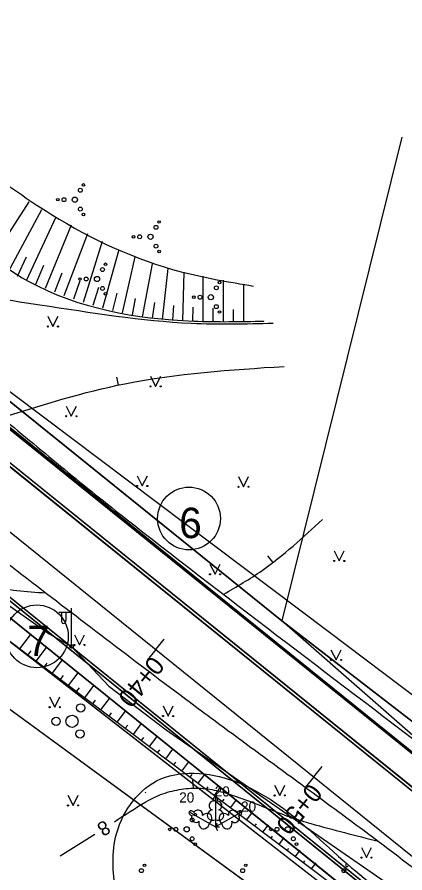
# Model space of a CAD drawing. Extents: x 514086 to 514457, y 297399 to 297567.
# Drawn here: x 514162.8 to 514181.92, y 297461.26 to 297503.43 of the extents above; entities that cross this region are included whole.
import ezdxf

# ---------------------------------------------------------------- set-up
doc = ezdxf.new("R2010")
doc.units = 0
for name, color, linetype in [('AA_Apzimejumi', 7, 'Continuous'), ('AA_Brauktuve', 7, 'Continuous'), ('AA_cela_mala', 7, 'Continuous'), ('AA_Ielas_ass', 7, 'Continuous'), ('AA_Ietve', 7, 'Continuous'), ('AA_nogaze', 7, 'Continuous'), ('AA_Nomale', 7, 'Continuous'), ('AA_Zale', 7, 'Continuous'), ('Level 1', 7, 'Continuous'), ('Level 21', 7, 'Continuous'), ('Level 23', 7, 'Continuous'), ('Level 29', 7, 'Continuous'), ('Level 31', 7, 'Continuous'), ('Level 32', 7, 'Continuous'), ('Level 37', 7, 'Continuous'), ('Level 44', 7, 'Continuous'), ('Level 45', 7, 'Continuous'), ('Level 46', 7, 'Continuous'), ('Level 8', 7, 'Continuous')]:
    doc.layers.add(name, color=color, linetype=linetype)

msp = doc.modelspace()

# ---------------------------------------------------------------- linework, layer by layer
at = {"layer": 'AA_Apzimejumi'}
for centre in [(514171.276, 297478.727), (514163.781, 297472.919)]:
    msp.add_circle(centre, 1.546, dxfattribs=at)
at = {"layer": 'AA_Brauktuve'}
for points in [[(514184.371, 297463.607), (514146.894, 297493.805)], [(514139.852, 297493.058), (514181.234, 297459.714)]]:
    msp.add_lwpolyline(points, dxfattribs=at)
at = {"layer": 'AA_cela_mala'}
for p, q in [((514185.262, 297464.713), (514147.785, 297494.911)), ((514147.835, 297494.973), (514185.313, 297464.775)), ((514146.894, 297493.805), (514184.371, 297463.607)), ((514184.466, 297463.724), (514146.988, 297493.922)), ((514139.758, 297492.942), (514181.14, 297459.597)), ((514139.852, 297493.058), (514181.234, 297459.714))]:
    msp.add_line(p, q, dxfattribs=at)
at = {"layer": 'AA_Ielas_ass'}
for p, q in [((514159.568, 297480.383), (514182.803, 297461.661)), ((514169.637, 297472.27), (514170.05, 297472.782)), ((514169.637, 297472.27), (514169.224, 297471.757)), ((514177.423, 297465.995), (514177.836, 297466.508)), ((514177.423, 297465.995), (514177.011, 297465.483))]:
    msp.add_line(p, q, dxfattribs=at)
at = {"layer": 'AA_Ietve'}
for points in [[(514185.262, 297464.713), (514147.791, 297494.906)], [(514146.982, 297493.927), (514184.466, 297463.724)]]:
    msp.add_lwpolyline(points, dxfattribs=at)
at = {"layer": 'AA_nogaze'}
for p, q in [((514162.943, 297472.302), (514163.47, 297473.001)), ((514163.343, 297472.001), (514163.498, 297472.207)), ((514163.742, 297471.7), (514164.249, 297472.373)), ((514164.54, 297471.098), (514165.028, 297471.745)), ((514164.141, 297471.399), (514164.29, 297471.597)), ((514164.939, 297470.797), (514165.083, 297470.988)), ((514165.339, 297470.496), (514165.807, 297471.117)), ((514165.738, 297470.195), (514165.876, 297470.378)), ((514166.137, 297469.894), (514166.586, 297470.49)), ((514166.536, 297469.593), (514166.668, 297469.768)), ((514166.936, 297469.292), (514167.365, 297469.862)), ((514167.335, 297468.991), (514167.461, 297469.158)), ((514167.734, 297468.69), (514168.144, 297469.234)), ((514168.133, 297468.389), (514168.254, 297468.549)), ((514168.533, 297468.088), (514168.923, 297468.606)), ((514168.932, 297467.787), (514169.046, 297467.939)), ((514169.331, 297467.486), (514169.702, 297467.979)), ((514169.73, 297467.185), (514169.839, 297467.329)), ((514170.13, 297466.884), (514170.482, 297467.352)), ((514170.529, 297466.583), (514170.632, 297466.721)), ((514170.928, 297466.282), (514171.266, 297466.731)), ((514171.327, 297465.981), (514171.427, 297466.113)), ((514171.727, 297465.68), (514172.051, 297466.11)), ((514172.126, 297465.379), (514172.221, 297465.505)), ((514172.525, 297465.078), (514172.835, 297465.49)), ((514172.924, 297464.777), (514173.015, 297464.898)), ((514173.323, 297464.476), (514173.62, 297464.869)), ((514173.723, 297464.175), (514173.809, 297464.29)), ((514174.122, 297463.874), (514174.404, 297464.248)), ((514174.521, 297463.573), (514174.604, 297463.682)), ((514174.92, 297463.272), (514175.188, 297463.627)), ((514175.32, 297462.971), (514175.398, 297463.075)), ((514175.719, 297462.67), (514175.973, 297463.007)), ((514176.118, 297462.369), (514176.192, 297462.467)), ((514176.517, 297462.068), (514176.757, 297462.386)), ((514176.917, 297461.767), (514176.986, 297461.86)), ((514177.316, 297461.466), (514177.542, 297461.765))]:
    msp.add_line(p, q, dxfattribs=at)
msp.add_lwpolyline([(514139.381, 297492.411), (514153.448, 297479.653), (514157.356, 297476.515), (514190.113, 297451.817)], dxfattribs=at)
at = {"layer": 'AA_Nomale'}
for points in [[(514181.14, 297459.597), (514139.77, 297492.933)], [(514139.413, 297492.389), (514139.411, 297492.386), (514180.732, 297459.091)]]:
    msp.add_lwpolyline(points, dxfattribs=at)
at = {"layer": 'AA_Zale'}
for p, q in [((514146.591, 297497.26), (514175.859, 297473.677)), ((514139.35, 297492.435), (514180.732, 297459.091)), ((514175.859, 297473.677), (514193.845, 297459.804))]:
    msp.add_line(p, q, dxfattribs=at)
for points in [[(514197.26, 297461.293), (514196.873, 297461.611), (514193.845, 297459.804), (514175.859, 297473.677), (514146.591, 297497.26)], [(514147.835, 297494.973), (514185.313, 297464.775)], [(514180.732, 297459.091), (514139.411, 297492.386), (514139.381, 297492.411)], [(514139.036, 297492.046), (514153.448, 297479.653), (514180.419, 297458.702)], [(514139.139, 297491.971), (514139.135, 297491.966), (514153.455, 297479.647), (514180.419, 297458.702)]]:
    msp.add_lwpolyline(points, dxfattribs=at)
at = {"layer": 'Level 1'}
for p, q in [((514172.279, 297463.703), (514172.58, 297463.53)), ((514172.58, 297463.877), (514172.58, 297463.53)), ((514172.58, 297463.53), (514172.68, 297463.703)), ((514172.881, 297463.703), (514172.58, 297463.53)), ((514172.58, 297463.53), (514172.78, 297463.53)), ((514172.58, 297463.53), (514172.68, 297463.357))]:
    msp.add_line(p, q, dxfattribs=at)
for points in [[(514172.58, 297465.03), (514172.58, 297463.877)], [(514172.67, 297464.798), (514172.669, 297464.799)], [(514171.281, 297464.28), (514172.279, 297463.703)], [(514171.527, 297464.241), (514171.526, 297464.241)], [(514173.879, 297464.28), (514172.881, 297463.703)], [(514173.723, 297464.086), (514173.723, 297464.088)]]:
    msp.add_lwpolyline(points, dxfattribs=at)
for centre, radius in [((514165.936, 297469.392), 0.207), ((514164.725, 297468.732), 0.204), ((514165.509, 297468.732), 0.301), ((514165.904, 297468.112), 0.205)]:
    msp.add_circle(centre, radius, dxfattribs=at)
for centre, major_axis, ratio, start_param, end_param in [((514172.58, 297464.88), (0, -0.15), 0.707107, 3.14537, 5.287485), ((514172.58, 297464.88), (0, -0.15), 0.707107, 0.995701, 3.137816), ((514172.452, 297464.585), (-0.039, -0.212), 0.861323, 3.141593, 6.283185), ((514172.708, 297464.585), (0.039, -0.212), 0.861323, 0, 3.141593), ((514171.411, 297464.205), (0.13, -0.075), 0.707107, 3.14537, 5.287485), ((514171.411, 297464.205), (0.13, -0.075), 0.707107, 0.995701, 3.137816), ((514171.602, 297463.946), (0.165, -0.14), 0.861323, 3.141593, 6.283185), ((514171.73, 297464.169), (0.203, -0.073), 0.861323, 0, 3.141593), ((514172.111, 297463.904), (-0.236, -0.218), 0.814445, 1.531171, 4.712389), ((514172.49, 297464.123), (0.307, 0.095), 0.814445, 1.570796, 4.752015), ((514172.67, 297464.123), (-0.307, 0.095), 0.814445, 1.531171, 4.712389), ((514173.049, 297463.904), (0.236, -0.218), 0.814445, 1.570796, 4.752015), ((514173.43, 297464.169), (-0.203, -0.073), 0.861323, 3.141593, 6.283185), ((514173.558, 297463.946), (-0.165, -0.14), 0.861323, 0, 3.141593), ((514173.749, 297464.205), (-0.13, -0.075), 0.707107, 3.14537, 5.287485), ((514173.749, 297464.205), (-0.13, -0.075), 0.707107, 0.995701, 3.137816), ((514172.022, 297463.749), (0.071, 0.313), 0.814445, 1.570796, 4.752015), ((514173.138, 297463.749), (-0.071, 0.313), 0.814445, 1.531171, 4.712389)]:
    msp.add_ellipse(centre, major_axis=major_axis, ratio=ratio, start_param=start_param, end_param=end_param, dxfattribs=at)
at = {"layer": 'Level 21'}
for points in [[(514157.951, 297499.728), (514156.119, 297498.271), (514154.804, 297496.296), (514155.649, 297494.512), (514158.938, 297490.653), (514163.925, 297489.256), (514171.388, 297488.349), (514175.429, 297488.349)], [(514167.656, 297460.196), (514167.656, 297463.017), (514169.677, 297465.792), (514173.482, 297465.792), (514178.65, 297462.077), (514185.698, 297456.857), (514187.671, 297455.211), (514188.469, 297452.531), (514186.966, 297450.274), (514184.429, 297447.265)]]:
    msp.add_spline(points, degree=3, dxfattribs=at)
at = {"layer": 'Level 23'}
for p, q in [((514164.32, 297488.688), (514164.57, 297488.188)), ((514164.57, 297488.188), (514164.82, 297488.688)), ((514169.38, 297485.735), (514169.63, 297485.235)), ((514169.63, 297485.235), (514169.88, 297485.735)), ((514165.226, 297484.266), (514165.476, 297483.766)), ((514165.476, 297483.766), (514165.726, 297484.266)), ((514168.724, 297480.828), (514168.974, 297480.328)), ((514168.974, 297480.328), (514169.224, 297480.828)), ((514173.714, 297480.789), (514173.964, 297480.289)), ((514173.964, 297480.289), (514174.214, 297480.789)), ((514178.43, 297477.133), (514178.68, 297476.633)), ((514178.68, 297476.633), (514178.93, 297477.133)), ((514172.308, 297476.476), (514172.558, 297475.976)), ((514172.558, 297475.976), (514172.808, 297476.476)), ((514165.624, 297472.994), (514165.874, 297472.494)), ((514165.874, 297472.494), (514166.124, 297472.994)), ((514178.274, 297472.258), (514178.524, 297471.758)), ((514178.524, 297471.758), (514178.774, 297472.258)), ((514164.406, 297469.932), (514164.656, 297469.432)), ((514164.656, 297469.432), (514164.906, 297469.932)), ((514169.996, 297469.494), (514170.246, 297468.994)), ((514170.246, 297468.994), (514170.496, 297469.494)), ((514175.497, 297465.58), (514175.747, 297465.08)), ((514175.747, 297465.08), (514175.997, 297465.58)), ((514165.311, 297465.088), (514165.561, 297464.588)), ((514165.561, 297464.588), (514165.811, 297465.088)), ((514179.776, 297462.517), (514180.026, 297462.017)), ((514180.026, 297462.017), (514180.276, 297462.517))]:
    msp.add_line(p, q, dxfattribs=at)
for centre, radius in [((514166.07, 297495.161), 0.064), ((514165.918, 297494.898), 0.096), ((514164.811, 297494.434), 0.064), ((514165.114, 297494.434), 0.096), ((514165.65, 297494.434), 0.128), ((514165.918, 297493.97), 0.096), ((514166.07, 297493.707), 0.064), ((514169.65, 297493.071), 0.096), ((514169.801, 297493.334), 0.064), ((514168.846, 297492.607), 0.096), ((514169.382, 297492.607), 0.128), ((514168.542, 297492.607), 0.064), ((514169.65, 297492.143), 0.096), ((514169.801, 297491.88), 0.064), ((514167.011, 297490.989), 0.096), ((514167.163, 297491.252), 0.064), ((514165.904, 297490.525), 0.064), ((514166.208, 297490.525), 0.096), ((514166.743, 297490.525), 0.128), ((514172.624, 297490.091), 0.096), ((514172.776, 297490.354), 0.064), ((514167.011, 297490.061), 0.096), ((514167.163, 297489.798), 0.064), ((514172.356, 297489.627), 0.128), ((514171.516, 297489.627), 0.064), ((514171.82, 297489.627), 0.096), ((514172.624, 297489.163), 0.096), ((514172.776, 297488.9), 0.064), ((514164.32, 297488.187), 0.028), ((514164.82, 297488.187), 0.0263), ((514169.38, 297485.234), 0.028), ((514169.88, 297485.234), 0.0263), ((514165.226, 297483.765), 0.028), ((514165.726, 297483.765), 0.0263), ((514168.724, 297480.328), 0.028), ((514169.224, 297480.328), 0.0263), ((514173.714, 297480.289), 0.028), ((514174.214, 297480.289), 0.0263), ((514178.43, 297476.632), 0.028), ((514178.93, 297476.632), 0.0263), ((514172.308, 297475.976), 0.028), ((514172.808, 297475.976), 0.0263), ((514165.623, 297472.494), 0.028), ((514166.123, 297472.494), 0.0263), ((514178.274, 297471.757), 0.028), ((514178.774, 297471.757), 0.0263), ((514164.405, 297469.431), 0.028), ((514164.905, 297469.431), 0.0263), ((514169.996, 297468.994), 0.028), ((514170.496, 297468.994), 0.0263), ((514175.497, 297465.08), 0.028), ((514175.997, 297465.08), 0.0263), ((514165.311, 297464.587), 0.028), ((514165.811, 297464.587), 0.0263), ((514171.582, 297464.135), 0.064), ((514171.43, 297463.872), 0.096), ((514170.323, 297463.408), 0.064), ((514170.626, 297463.408), 0.096), ((514171.162, 297463.408), 0.128), ((514175.312, 297463.408), 0.064), ((514175.615, 297463.408), 0.096), ((514176.151, 297463.408), 0.128), ((514171.43, 297462.944), 0.096), ((514176.419, 297462.944), 0.096), ((514171.582, 297462.681), 0.064), ((514176.571, 297462.681), 0.064), ((514179.776, 297462.017), 0.028), ((514180.276, 297462.017), 0.0263), ((514169.082, 297461.635), 0.064), ((514174.071, 297461.635), 0.064), ((514168.93, 297461.372), 0.096), ((514173.919, 297461.372), 0.096), ((514178.908, 297461.372), 0.096)]:
    msp.add_circle(centre, radius, dxfattribs=at)
for centre, start, end in [((514169.082, 297465.266), 308.5918, 335.9048), ((514179.06, 297461.635), 133.9425, 333.2997)]:
    msp.add_arc(centre, 0.064, start, end, dxfattribs=at)
at = {"layer": 'Level 29'}
for p, q in [((514139.316, 297503.122), (514175.859, 297473.677)), ((514181.77, 297497.508), (514175.859, 297473.677)), ((514139.134, 297486.37), (514229.261, 297420.493))]:
    msp.add_line(p, q, dxfattribs=at)
at = {"layer": 'Level 31'}
for p, q in [((514161.521, 297491.416), (514163.395, 297494.328)), ((514162.378, 297490.903), (514164.024, 297493.957)), ((514163.274, 297490.458), (514164.733, 297493.583)), ((514164.196, 297490.073), (514165.485, 297493.19)), ((514165.13, 297489.714), (514166.287, 297492.771)), ((514166.075, 297489.389), (514167.009, 297492.394)), ((514167.033, 297489.103), (514167.835, 297491.974)), ((514162.821, 297490.669), (514163.261, 297491.613)), ((514168.003, 297488.859), (514168.618, 297491.616)), ((514163.734, 297490.264), (514164.126, 297491.211)), ((514168.984, 297488.668), (514169.471, 297491.279)), ((514169.975, 297488.533), (514170.25, 297491.038)), ((514164.662, 297489.891), (514165.016, 297490.825)), ((514170.972, 297488.463), (514171.031, 297490.858)), ((514171.972, 297488.45), (514171.972, 297490.672)), ((514165.602, 297489.549), (514165.915, 297490.459)), ((514172.972, 297488.45), (514172.972, 297490.474)), ((514173.972, 297488.45), (514173.972, 297490.277)), ((514166.553, 297489.24), (514166.825, 297490.116)), ((514167.517, 297488.975), (514167.728, 297489.82)), ((514168.493, 297488.759), (514168.644, 297489.569)), ((514169.479, 297488.594), (514169.589, 297489.362)), ((514170.473, 297488.491), (514170.526, 297489.226)), ((514171.472, 297488.451), (514171.489, 297489.143)), ((514172.472, 297488.45), (514172.472, 297489.087)), ((514173.472, 297488.45), (514173.472, 297489.028)), ((514174.472, 297488.45), (514174.472, 297488.453)), ((514174.972, 297488.45), (514174.972, 297488.46))]:
    msp.add_line(p, q, dxfattribs=at)
for points in [[(514148.099, 297499.821), (514150.307, 297498.081), (514154.61, 297496.51), (514163.344, 297490.425), (514171.508, 297488.45), (514174.972, 297488.45)], [(514148.099, 297499.821), (514150.886, 297499.489), (514156.496, 297498.491), (514164.495, 297493.708), (514170.885, 297490.886), (514174.455, 297490.181)]]:
    msp.add_spline(points, degree=3, dxfattribs=at)
at = {"layer": 'Level 32'}
for p, q in [((514167.8, 297485.304), (514167.719, 297485.696)), ((514175.402, 297476.567), (514175.155, 297476.882)), ((514171.498, 297465.436), (514171.463, 297465.835)), ((514164.926, 297462.105), (514166.631, 297463.177))]:
    msp.add_line(p, q, dxfattribs=at)
for points in [[(514162.045, 297483.701), (514168.12, 297485.367), (514175.973, 297486.222)], [(514172.994, 297474.997), (514174.877, 297476.167), (514177.854, 297478.68)], [(514154.132, 297474.229), (514154.967, 297472.986), (514156.01, 297472.272), (514156.777, 297472.814), (514156.486, 297474.559), (514156.01, 297476.158), (514157.426, 297476.912), (514161.437, 297475.49), (514164.213, 297475.068)], [(514167.597, 297463.785), (514169.156, 297464.765), (514169.557, 297464.985), (514169.986, 297465.162), (514170.901, 297465.386), (514171.84, 297465.432), (514172.298, 297465.388), (514172.739, 297465.297), (514173.876, 297464.933), (514175.003, 297464.498), (514176.136, 297464.061), (514176.709, 297463.865), (514177.288, 297463.695), (514180.611, 297462.82)]]:
    msp.add_spline(points, degree=3, dxfattribs=at)
at = {"layer": 'Level 37'}
for points in [[(514139.874, 297497.035), (514148.452, 297493.087), (514152.9, 297490.654), (514155.012, 297489.24), (514157.055, 297487.727), (514160.163, 297485.252), (514163.225, 297482.729), (514166.288, 297480.21), (514169.399, 297477.75), (514184.679, 297466.049), (514188.685, 297462.979), (514190.692, 297461.445), (514192.708, 297459.912), (514193.134, 297459.688), (514193.613, 297459.574), (514194.114, 297459.524), (514194.606, 297459.489), (514195.045, 297459.442), (514195.506, 297459.417), (514195.979, 297459.548), (514196.259, 297459.707)], [(514136.849, 297494.086), (514140.775, 297492.444), (514142.699, 297491.153), (514143.967, 297490.173), (514145.225, 297489.179), (514146.485, 297488.19), (514147.764, 297487.226), (514149.635, 297485.885), (514151.52, 297484.563), (514153.402, 297483.236), (514155.263, 297481.88), (514159.161, 297478.934), (514163.043, 297475.965), (514166.923, 297472.996), (514170.82, 297470.048), (514173.26, 297468.237), (514175.709, 297466.438), (514178.159, 297464.639), (514180.6, 297462.828), (514184.429, 297459.874), (514186.323, 297458.371), (514188.215, 297456.863), (514189.034, 297456.154), (514191.11, 297453.709)]]:
    msp.add_spline(points, degree=3, dxfattribs=at)
at = {"layer": 'Level 44'}
for p, q in [((514165.491, 297472.425), (514165.491, 297474.308)), ((514165.491, 297474.088), (514164.856, 297474.088)), ((514164.991, 297474.088), (514164.991, 297473.696)), ((514165.201, 297474.088), (514165.201, 297473.696))]:
    msp.add_line(p, q, dxfattribs=at)
msp.add_circle((514165.491, 297472.425), 0.09, dxfattribs=at)
msp.add_ellipse((514165.096, 297473.696), major_axis=(0, 0.151), ratio=0.695971, start_param=1.570796, end_param=4.712389, dxfattribs=at)
at = {"layer": 'Level 45'}
for points in [[(514142.645, 297489.455), (514144.367, 297488.114), (514148.432, 297484.764), (514152.497, 297481.414), (514158.438, 297477.231), (514164.38, 297473.048), (514165.491, 297472.425)], [(514165.491, 297472.425), (514167.329, 297470.46), (514170.146, 297468.31), (514175.888, 297464.328), (514181.629, 297460.345), (514185.517, 297457.375), (514189.404, 297454.406)]]:
    msp.add_lwpolyline(points, dxfattribs=at)
at = {"layer": 'Level 46'}
msp.add_lwpolyline([(514139.134, 297486.37), (514229.261, 297420.493), (514237.863, 297414.208), (514250.009, 297428.181), (514295.433, 297494.723), (514312.775, 297524.542), (514316.491, 297528.738), (514320.446, 297531.016), (514328.236, 297532.215), (514332.539, 297530.572), (514332.631, 297530.536), (514341.642, 297542.18), (514320.211, 297553.997), (514285.885, 297496.27), (514243.195, 297433.696), (514241.534, 297432.407), (514239.451, 297432.203), (514209.969, 297445.237), (514194.45, 297457.413), (514175.859, 297473.677), (514139.316, 297503.122), (514133.046, 297508.174), (514130.604, 297489.221)], close=True, dxfattribs=at)
at = {"layer": 'Level 8'}
msp.add_lwpolyline([(514200.623, 297456.189), (514178.139, 297473.151), (514155.647, 297490.079), (514143.111, 297496.557), (514135.656, 297500), (514119.377, 297505.512), (514108.036, 297513.213), (514096.037, 297522.278)], dxfattribs=at)

# ---------------------------------------------------------------- texts
at = {"layer": 'AA_Apzimejumi'}
for s, p in [('6', (514170.79, 297477.758)), ('7', (514163.295, 297471.95))]:
    msp.add_text(s, height=1.5, dxfattribs=at).set_placement(p)
at = {"layer": 'AA_Ielas_ass'}
for s, p in [(' 0+40', (514169.637, 297472.27)), (' 0+50', (514177.423, 297465.995))]:
    msp.add_text(s, height=0.9, rotation=231.1394, dxfattribs=at).set_placement(p)
at = {"layer": 'Level 1'}
for p in [(514172.355, 297465.03), (514170.606, 297464.73), (514173.654, 297464.28)]:
    msp.add_text(' 20', height=0.5, dxfattribs=at).set_placement(p)
at = {"layer": 'Level 32'}
msp.add_text('8', height=0.7, rotation=211.2604, dxfattribs=at).set_placement((514167.121, 297463.895))

doc.saveas('drawing.dxf')
